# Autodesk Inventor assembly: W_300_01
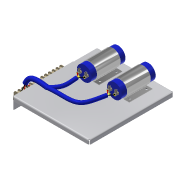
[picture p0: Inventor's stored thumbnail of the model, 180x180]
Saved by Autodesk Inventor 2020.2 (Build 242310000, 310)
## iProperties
Created: 2014-09
Part Number: W_300_01
Document SubType Name: Assembly
Designer: F.Stasiak
Catalog Web Link: www.expertbooks.pl
Manager: www.cadconsulting.pl
Company: Fabian Stasiak CAD Consulting
Author: F.Stasiak
Subject: Zbiór ćwiczeń. Autodesk Inventor 2020. Kurs Professional
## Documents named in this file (5)
- C:\2020_Kurs_Professional\R2 Wiązki\W_300_01.iam
- C:\2020_Kurs_Professional\R2 Wiązki\Komponenty\Podstawa_300_01.ipt
- C:\2020_Kurs_Professional\R2 Wiązki\Komponenty\KOND_350_2300.ipt
- C:\2020_Kurs_Professional\R2 Wiązki\W_300_01\AIP\przewody i wiązki przewodów\W_300_01.Wiązka przewodów1.iam
- C:\2020_Kurs_Professional\R2 Wiązki\Komponenty\LISTWA_100_01.ipt
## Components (5 placed, 4 different names)
1. Podstawa_300_01:1 — Zestawiający:1, Zestawiający:2, Równoległy:2, Zestawiający:3, Równoległy:3, Równoległy:4
2. KOND_350_2300:1 — Zestawiający:1, Równoległy:1
3. KOND_350_2300:2 — Zestawiający:2, Równoległy:1, Równoległy:2
4. LISTWA_100_01:1 — Zestawiający:3, Równoległy:3, Równoległy:4
5. Wiązka przewodów1 [sub-assembly]
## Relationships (7: Flush 4, Mate 3)
- Zestawiający:1 [Mate]: Podstawa_300_01:1 ↔ KOND_350_2300:1
- Zestawiający:2 [Mate]: Podstawa_300_01:1 ↔ KOND_350_2300:2
- Równoległy:1 [Flush]: KOND_350_2300:1 ↔ KOND_350_2300:2
- Równoległy:2 [Flush]: Podstawa_300_01:1 ↔ KOND_350_2300:2
- Zestawiający:3 [Mate]: Podstawa_300_01:1 ↔ LISTWA_100_01:1
- Równoległy:3 [Flush]: Podstawa_300_01:1 ↔ LISTWA_100_01:1
- Równoległy:4 [Flush]: Podstawa_300_01:1 ↔ LISTWA_100_01:1
